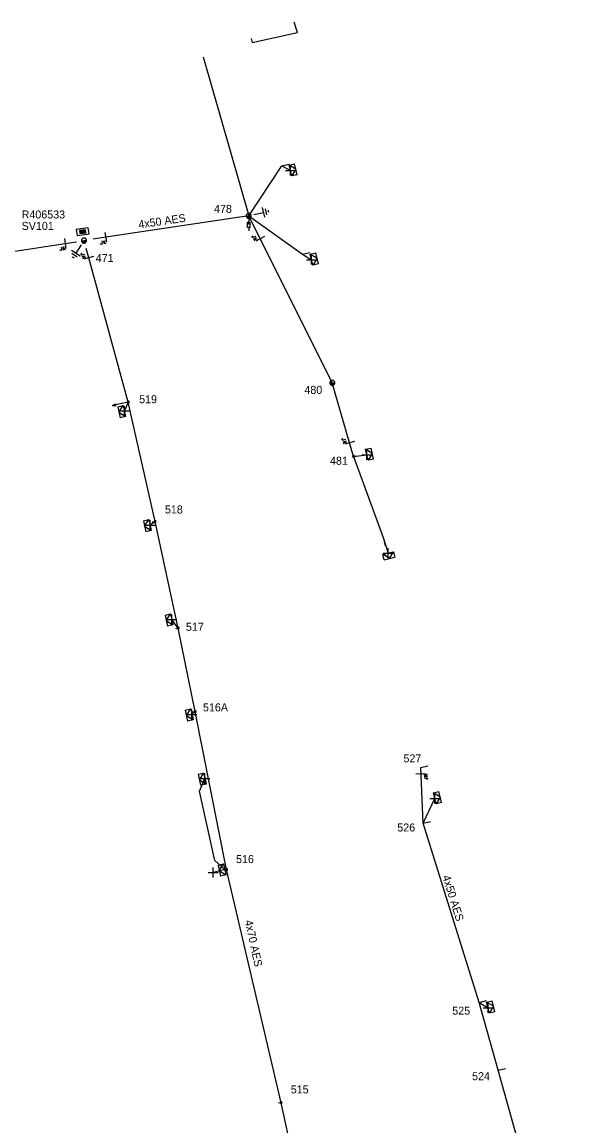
# Model space of a CAD drawing. Extents: x -540466 to -537383, y -1184038 to -1179972.
# Drawn here: x -539090.8 to -539022.6, y -1180402.2 to -1180264.3 of the extents above; entities that cross this region are included whole.
import ezdxf

# ---------------------------------------------------------------- set-up
doc = ezdxf.new("R2010")
doc.units = 0
for name, color, linetype in [('Vrstva 1', 7, 'Continuous'), ('Vrstva 13', 7, 'Continuous'), ('Vrstva 14', 7, 'Continuous'), ('Vrstva 15', 7, 'Continuous'), ('Vrstva 16', 7, 'Continuous'), ('Vrstva 18', 7, 'Continuous'), ('Vrstva 2', 7, 'Continuous'), ('Vrstva 28', 7, 'Continuous'), ('Vrstva 29', 7, 'Continuous'), ('Vrstva 30', 7, 'Continuous'), ('Vrstva 31', 7, 'Continuous'), ('Vrstva 34', 7, 'Continuous'), ('Vrstva 50', 7, 'Continuous'), ('Vrstva 51', 7, 'Continuous'), ('Vrstva 52', 7, 'Continuous'), ('Vrstva 54', 7, 'Continuous'), ('Vrstva 59', 7, 'Continuous'), ('Vrstva 8', 7, 'Continuous'), ('Vrstva 9', 7, 'Continuous')]:
    doc.layers.add(name, color=color, linetype=linetype)

# ---------------------------------------------------------------- blocks, each defined once
blk = doc.blocks.new('NN440')
at = {"layer": 'Vrstva 2'}
for points in [[(0.63, 0), (0.63, 0.06), (0.62, 0.13), (0.6, 0.19), (0.58, 0.25), (0.55, 0.31), (0.51, 0.37), (0.47, 0.42), (0.42, 0.46), (0.37, 0.51), (0.32, 0.54), (0.26, 0.57), (0.2, 0.59), (0.13, 0.61), (0.07, 0.62), (0, 0.63), (-0.06, 0.62), (-0.13, 0.61), (-0.19, 0.59), (-0.26, 0.57), (-0.31, 0.54), (-0.37, 0.51), (-0.42, 0.46), (-0.47, 0.42), (-0.51, 0.37), (-0.54, 0.31), (-0.57, 0.25), (-0.6, 0.19), (-0.62, 0.13), (-0.63, 0.06), (-0.63, 0), (-0.63, -0.07), (-0.62, -0.14), (-0.6, -0.2), (-0.57, -0.26), (-0.54, -0.32), (-0.51, -0.37), (-0.47, -0.43), (-0.42, -0.47), (-0.37, -0.51), (-0.31, -0.55), (-0.26, -0.58), (-0.19, -0.6), (-0.13, -0.62), (-0.06, -0.63), (0, -0.63), (0.07, -0.63), (0.13, -0.62), (0.2, -0.6), (0.26, -0.58), (0.32, -0.55), (0.37, -0.51), (0.42, -0.47), (0.47, -0.43), (0.51, -0.37), (0.55, -0.32), (0.58, -0.26), (0.6, -0.2), (0.62, -0.14), (0.63, -0.07), (0.63, 0)], [(-0.63, 0), (0.63, 0)], [(-0.6, -0.18), (0.57, -0.18)], [(-0.51, -0.32), (0.5, -0.32)], [(-0.37, -0.47), (0.35, -0.47)]]:
    blk.add_lwpolyline(points, dxfattribs=at)
blk = doc.blocks.new('NN560')
at = {"layer": 'Vrstva 2'}
for points in [[(2, 0), (1.59, 0.14)], [(0, 0), (2, 0)], [(2, 0), (1.59, -0.13)]]:
    blk.add_lwpolyline(points, dxfattribs=at)
blk = doc.blocks.new('NN840')
at = {"layer": 'Vrstva 15'}
for points in [[(0, 0.62), (0, -0.63)], [(-0.75, -0.71), (-0.75, -0.66)], [(-0.73, -0.76), (-0.75, -0.71)], [(-0.66, -0.8), (-0.73, -0.76)], [(-0.63, -0.8), (-0.66, -0.8)], [(-0.56, -0.76), (-0.63, -0.8)], [(-0.54, -0.71), (-0.56, -0.76)], [(-0.54, -0.38), (-0.54, -0.71)], [(-0.33, -0.38), (-0.33, -0.8)], [(-0.33, -0.64), (-0.13, -0.38)], [(-0.26, -0.56), (-0.09, -0.8)]]:
    blk.add_lwpolyline(points, dxfattribs=at)
blk = doc.blocks.new('NN800')
at = {"layer": 'Vrstva 1'}
for points in [[(-0.44, 0.44), (0.44, -0.44)], [(-0.44, -0.44), (0.44, 0.44)]]:
    blk.add_lwpolyline(points, dxfattribs=at)
blk = doc.blocks.new('NN820')
at = {"layer": 'Vrstva 13'}
for points in [[(0, 0), (0, -1.05)], [(-0.16, -0.81), (0.16, -0.81)], [(-0.16, -1.47), (-0.16, -0.81)], [(0, -1.05), (-0.06, -0.93)], [(0, -1.05), (0.06, -0.93)], [(0.16, -0.81), (0.16, -1.47)], [(0.16, -1.47), (-0.16, -1.47)], [(0, -1.47), (0, -1.87)]]:
    blk.add_lwpolyline(points, dxfattribs=at)
blk = doc.blocks.new('NN620')
at = {"layer": 'Vrstva 8'}
for points in [[(0.75, 0), (-0.75, 0)], [(-0.75, 0), (-0.75, -0.75)], [(0.75, -0.75), (0.75, 0)], [(-0.75, -0.75), (0.75, -0.75)], [(0.37, -0.18), (-0.38, -0.18)], [(-0.38, -0.18), (-0.38, -0.56)], [(-0.38, -0.56), (0.37, -0.56)], [(0.32, -0.23), (-0.33, -0.23)], [(-0.33, -0.23), (-0.33, -0.51)], [(-0.33, -0.51), (0.32, -0.51)], [(0.27, -0.27), (-0.28, -0.27)], [(-0.28, -0.27), (-0.28, -0.46)], [(-0.28, -0.46), (0.27, -0.46)], [(0.23, -0.32), (-0.23, -0.32)], [(-0.23, -0.32), (-0.23, -0.42)], [(-0.23, -0.42), (0.23, -0.42)], [(-0.19, -0.37), (0.19, -0.37)], [(0.23, -0.42), (0.23, -0.32)], [(0.27, -0.46), (0.27, -0.27)], [(0.32, -0.51), (0.32, -0.23)], [(0.37, -0.56), (0.37, -0.18)]]:
    blk.add_lwpolyline(points, dxfattribs=at)
blk = doc.blocks.new('NN630')
at = {"layer": 'Vrstva 9'}
for points in [[(0, -0.7), (-0.7, 0)], [(-0.7, -0.7), (-0.7, 0), (0.7, 0), (0.7, -0.7)], [(-0.7, -0.7), (0.7, -0.7)], [(0, -0.7), (0.7, 0)]]:
    blk.add_lwpolyline(points, dxfattribs=at)
blk = doc.blocks.new('NN810')
at = {"layer": 'Vrstva 14'}
for points in [[(0, -0.64), (0, -1.89)], [(0.63, -1.89), (-0.62, -1.89)], [(0.39, -2.2), (-0.4, -2.2)], [(0, -2.52), (-0.12, -2.52)], [(0.14, -2.52), (0, -2.52)]]:
    blk.add_lwpolyline(points, dxfattribs=at)
blk = doc.blocks.new('NN500')
at = {"layer": 'Vrstva 2'}
for points in [[(0, -0.24), (0.02, -0.23), (0.05, -0.23), (0.07, -0.22), (0.09, -0.22), (0.12, -0.2), (0.14, -0.19), (0.16, -0.18), (0.17, -0.16), (0.19, -0.14), (0.2, -0.12), (0.21, -0.1), (0.22, -0.07), (0.23, -0.05), (0.23, -0.02), (0.23, 0), (0.23, 0.02), (0.23, 0.05), (0.22, 0.07), (0.21, 0.1), (0.2, 0.12), (0.19, 0.14), (0.17, 0.16), (0.16, 0.17), (0.14, 0.19), (0.12, 0.2), (0.09, 0.21), (0.07, 0.22), (0.05, 0.23), (0.02, 0.23), (0, 0.23), (-0.03, 0.23), (-0.05, 0.23), (-0.07, 0.22), (-0.1, 0.21), (-0.12, 0.2), (-0.14, 0.19), (-0.16, 0.17), (-0.18, 0.16), (-0.19, 0.14), (-0.2, 0.12), (-0.22, 0.1), (-0.22, 0.07), (-0.23, 0.05), (-0.23, 0.02), (-0.24, 0), (-0.23, -0.02), (-0.23, -0.05), (-0.22, -0.07), (-0.22, -0.1), (-0.2, -0.12), (-0.19, -0.14), (-0.18, -0.16), (-0.16, -0.18), (-0.14, -0.19), (-0.12, -0.2), (-0.1, -0.22), (-0.07, -0.22), (-0.05, -0.23), (-0.03, -0.23), (0, -0.24)], [(0, -0.24), (0.02, -0.23), (0.05, -0.23), (0.07, -0.22), (0.09, -0.22), (0.12, -0.2), (0.14, -0.19), (0.16, -0.18), (0.17, -0.16), (0.19, -0.14), (0.2, -0.12), (0.21, -0.1), (0.22, -0.07), (0.23, -0.05), (0.23, -0.02), (0.23, 0), (0.23, 0.02), (0.23, 0.05), (0.22, 0.07), (0.21, 0.1), (0.2, 0.12), (0.19, 0.14), (0.17, 0.16), (0.16, 0.17), (0.14, 0.19), (0.12, 0.2), (0.09, 0.21), (0.07, 0.22), (0.05, 0.23), (0.02, 0.23), (0, 0.23), (-0.03, 0.23), (-0.05, 0.23), (-0.07, 0.22), (-0.1, 0.21), (-0.12, 0.2), (-0.14, 0.19), (-0.16, 0.17), (-0.18, 0.16), (-0.19, 0.14), (-0.2, 0.12), (-0.22, 0.1), (-0.22, 0.07), (-0.23, 0.05), (-0.23, 0.02), (-0.24, 0), (-0.23, -0.02), (-0.23, -0.05), (-0.22, -0.07), (-0.22, -0.1), (-0.2, -0.12), (-0.19, -0.14), (-0.18, -0.16), (-0.16, -0.18), (-0.14, -0.19), (-0.12, -0.2), (-0.1, -0.22), (-0.07, -0.22), (-0.05, -0.23), (-0.03, -0.23), (0, -0.24)], [(0, -0.21), (0.02, -0.2), (0.04, -0.2), (0.06, -0.2), (0.08, -0.19), (0.1, -0.18), (0.12, -0.17), (0.14, -0.15), (0.15, -0.14), (0.16, -0.12), (0.18, -0.1), (0.19, -0.08), (0.19, -0.06), (0.2, -0.04), (0.2, -0.02), (0.2, 0), (0.2, 0.02), (0.2, 0.04), (0.19, 0.06), (0.19, 0.08), (0.18, 0.1), (0.16, 0.12), (0.15, 0.14), (0.14, 0.15), (0.12, 0.17), (0.1, 0.18), (0.08, 0.19), (0.06, 0.19), (0.04, 0.2), (0.02, 0.2), (0, 0.2), (-0.02, 0.2), (-0.04, 0.2), (-0.06, 0.19), (-0.08, 0.19), (-0.1, 0.18), (-0.12, 0.17), (-0.14, 0.15), (-0.15, 0.14), (-0.17, 0.12), (-0.18, 0.1), (-0.19, 0.08), (-0.2, 0.06), (-0.2, 0.04), (-0.21, 0.02), (-0.21, 0), (-0.21, -0.02), (-0.2, -0.04), (-0.2, -0.06), (-0.19, -0.08), (-0.18, -0.1), (-0.17, -0.12), (-0.15, -0.14), (-0.14, -0.15), (-0.12, -0.17), (-0.1, -0.18), (-0.08, -0.19), (-0.06, -0.2), (-0.04, -0.2), (-0.02, -0.2), (0, -0.21)], [(0, -0.18), (0.02, -0.18), (0.04, -0.17), (0.05, -0.17), (0.07, -0.16), (0.09, -0.15), (0.1, -0.14), (0.12, -0.13), (0.13, -0.12), (0.14, -0.1), (0.15, -0.09), (0.16, -0.07), (0.17, -0.05), (0.17, -0.04), (0.17, -0.02), (0.17, 0), (0.17, 0.02), (0.17, 0.04), (0.17, 0.05), (0.16, 0.07), (0.15, 0.09), (0.14, 0.1), (0.13, 0.12), (0.12, 0.13), (0.1, 0.14), (0.09, 0.15), (0.07, 0.16), (0.05, 0.17), (0.04, 0.17), (0.02, 0.17), (0, 0.18), (-0.02, 0.17), (-0.04, 0.17), (-0.06, 0.17), (-0.07, 0.16), (-0.09, 0.15), (-0.1, 0.14), (-0.12, 0.13), (-0.13, 0.12), (-0.14, 0.1), (-0.15, 0.09), (-0.16, 0.07), (-0.17, 0.05), (-0.17, 0.04), (-0.18, 0.02), (-0.18, 0), (-0.18, -0.02), (-0.17, -0.04), (-0.17, -0.05), (-0.16, -0.07), (-0.15, -0.09), (-0.14, -0.1), (-0.13, -0.12), (-0.12, -0.13), (-0.1, -0.14), (-0.09, -0.15), (-0.07, -0.16), (-0.06, -0.17), (-0.04, -0.17), (-0.02, -0.18), (0, -0.18)], [(0, -0.15), (0.01, -0.15), (0.03, -0.14), (0.04, -0.14), (0.06, -0.13), (0.07, -0.13), (0.08, -0.12), (0.1, -0.11), (0.11, -0.1), (0.12, -0.09), (0.13, -0.07), (0.13, -0.06), (0.14, -0.05), (0.14, -0.03), (0.14, -0.02), (0.14, 0), (0.14, 0.01), (0.14, 0.03), (0.14, 0.04), (0.13, 0.06), (0.13, 0.07), (0.12, 0.09), (0.11, 0.1), (0.1, 0.11), (0.08, 0.12), (0.07, 0.13), (0.06, 0.13), (0.04, 0.14), (0.03, 0.14), (0.01, 0.14), (0, 0.15), (-0.02, 0.14), (-0.03, 0.14), (-0.05, 0.14), (-0.06, 0.13), (-0.07, 0.13), (-0.09, 0.12), (-0.1, 0.11), (-0.11, 0.1), (-0.12, 0.09), (-0.13, 0.07), (-0.13, 0.06), (-0.14, 0.04), (-0.14, 0.03), (-0.15, 0.01), (-0.15, 0), (-0.15, -0.02), (-0.14, -0.03), (-0.14, -0.05), (-0.13, -0.06), (-0.13, -0.07), (-0.12, -0.09), (-0.11, -0.1), (-0.1, -0.11), (-0.09, -0.12), (-0.07, -0.13), (-0.06, -0.13), (-0.05, -0.14), (-0.03, -0.14), (-0.02, -0.15), (0, -0.15)], [(0, -0.12), (0.01, -0.12), (0.02, -0.11), (0.03, -0.11), (0.05, -0.11), (0.06, -0.1), (0.07, -0.09), (0.08, -0.09), (0.09, -0.08), (0.09, -0.07), (0.1, -0.06), (0.11, -0.05), (0.11, -0.04), (0.11, -0.02), (0.11, -0.01), (0.12, 0), (0.11, 0.01), (0.11, 0.02), (0.11, 0.04), (0.11, 0.05), (0.1, 0.06), (0.09, 0.07), (0.09, 0.08), (0.08, 0.09), (0.07, 0.09), (0.06, 0.1), (0.05, 0.11), (0.03, 0.11), (0.02, 0.11), (0.01, 0.12), (0, 0.12), (-0.01, 0.12), (-0.03, 0.11), (-0.04, 0.11), (-0.05, 0.11), (-0.06, 0.1), (-0.07, 0.09), (-0.08, 0.09), (-0.09, 0.08), (-0.1, 0.07), (-0.1, 0.06), (-0.11, 0.05), (-0.11, 0.04), (-0.12, 0.02), (-0.12, 0.01), (-0.12, 0), (-0.12, -0.01), (-0.12, -0.02), (-0.11, -0.04), (-0.11, -0.05), (-0.1, -0.06), (-0.1, -0.07), (-0.09, -0.08), (-0.08, -0.09), (-0.07, -0.09), (-0.06, -0.1), (-0.05, -0.11), (-0.04, -0.11), (-0.03, -0.11), (-0.01, -0.12), (0, -0.12)], [(0, -0.09), (0.01, -0.09), (0.02, -0.09), (0.03, -0.08), (0.03, -0.08), (0.04, -0.08), (0.05, -0.07), (0.06, -0.07), (0.06, -0.06), (0.07, -0.05), (0.07, -0.04), (0.08, -0.04), (0.08, -0.03), (0.08, -0.02), (0.09, -0.01), (0.09, 0), (0.09, 0.01), (0.08, 0.02), (0.08, 0.03), (0.08, 0.03), (0.07, 0.04), (0.07, 0.05), (0.06, 0.06), (0.06, 0.06), (0.05, 0.07), (0.04, 0.07), (0.03, 0.08), (0.03, 0.08), (0.02, 0.08), (0.01, 0.09), (0, 0.09), (-0.01, 0.09), (-0.02, 0.08), (-0.03, 0.08), (-0.04, 0.08), (-0.04, 0.07), (-0.05, 0.07), (-0.06, 0.06), (-0.07, 0.06), (-0.07, 0.05), (-0.08, 0.04), (-0.08, 0.03), (-0.08, 0.03), (-0.09, 0.02), (-0.09, 0.01), (-0.09, 0), (-0.09, -0.01), (-0.09, -0.02), (-0.08, -0.03), (-0.08, -0.04), (-0.08, -0.04), (-0.07, -0.05), (-0.07, -0.06), (-0.06, -0.07), (-0.05, -0.07), (-0.04, -0.08), (-0.04, -0.08), (-0.03, -0.08), (-0.02, -0.09), (-0.01, -0.09), (0, -0.09)], [(0, -0.06), (0, -0.06), (0.01, -0.06), (0.02, -0.05), (0.02, -0.05), (0.03, -0.05), (0.03, -0.05), (0.04, -0.04), (0.04, -0.04), (0.05, -0.03), (0.05, -0.03), (0.05, -0.02), (0.05, -0.02), (0.05, -0.01), (0.06, -0.01), (0.06, 0), (0.06, 0.01), (0.05, 0.01), (0.05, 0.02), (0.05, 0.02), (0.05, 0.03), (0.05, 0.03), (0.04, 0.04), (0.04, 0.04), (0.03, 0.05), (0.03, 0.05), (0.02, 0.05), (0.02, 0.05), (0.01, 0.06), (0, 0.06), (0, 0.06), (-0.01, 0.06), (-0.01, 0.06), (-0.02, 0.05), (-0.02, 0.05), (-0.03, 0.05), (-0.03, 0.05), (-0.04, 0.04), (-0.04, 0.04), (-0.05, 0.03), (-0.05, 0.03), (-0.05, 0.02), (-0.06, 0.02), (-0.06, 0.01), (-0.06, 0.01), (-0.06, 0), (-0.06, -0.01), (-0.06, -0.01), (-0.06, -0.02), (-0.05, -0.02), (-0.05, -0.03), (-0.05, -0.03), (-0.04, -0.04), (-0.04, -0.04), (-0.03, -0.05), (-0.03, -0.05), (-0.02, -0.05), (-0.02, -0.05), (-0.01, -0.06), (-0.01, -0.06), (0, -0.06)], [(0, -0.03), (0, -0.03), (0, -0.03), (0.01, -0.03), (0.01, -0.03), (0.01, -0.02), (0.02, -0.02), (0.02, -0.02), (0.02, -0.02), (0.02, -0.02), (0.02, -0.01), (0.02, -0.01), (0.03, -0.01), (0.03, -0.01), (0.03, 0), (0.03, 0), (0.03, 0), (0.03, 0.01), (0.03, 0.01), (0.02, 0.01), (0.02, 0.01), (0.02, 0.02), (0.02, 0.02), (0.02, 0.02), (0.02, 0.02), (0.01, 0.02), (0.01, 0.02), (0.01, 0.03), (0, 0.03), (0, 0.03), (0, 0.03), (0, 0.03), (-0.01, 0.03), (-0.01, 0.03), (-0.01, 0.02), (-0.02, 0.02), (-0.02, 0.02), (-0.02, 0.02), (-0.02, 0.02), (-0.02, 0.02), (-0.03, 0.01), (-0.03, 0.01), (-0.03, 0.01), (-0.03, 0.01), (-0.03, 0), (-0.03, 0), (-0.03, 0), (-0.03, -0.01), (-0.03, -0.01), (-0.03, -0.01), (-0.03, -0.01), (-0.02, -0.02), (-0.02, -0.02), (-0.02, -0.02), (-0.02, -0.02), (-0.02, -0.02), (-0.01, -0.03), (-0.01, -0.03), (-0.01, -0.03), (0, -0.03), (0, -0.03)], [(0.23, 0), (0.7, 0)]]:
    blk.add_lwpolyline(points, dxfattribs=at)
blk = doc.blocks.new('NN510')
at = {"layer": 'Vrstva 2'}
blk.add_lwpolyline([(0, 0), (0, 0.94)], dxfattribs=at)

msp = doc.modelspace()

# ---------------------------------------------------------------- linework, layer by layer
at = {"layer": 'Vrstva 50'}
for points in [[(-539068.11, -1180268.64), (-539062.44, -1180288.49)], [(-539062.44, -1180288.49), (-539080.31, -1180291.17), (-539081.87, -1180291.41)], [(-539146.42, -1180302.53), (-539117.6, -1180296.87), (-539085.38, -1180291.94), (-539083.95, -1180291.72)], [(-539056.32, -1180408.67), (-539058.39, -1180399.32), (-539065.2, -1180370.19), (-539069.12, -1180350.45), (-539071.24, -1180340.01), (-539074.14, -1180326.71), (-539077.49, -1180311.78), (-539082.43, -1180293.73), (-539082.75, -1180292.58)], [(-539022.55, -1180455.54), (-539022.63, -1180454.15), (-539024.54, -1180420.07), (-539028.02, -1180406.89), (-539031.25, -1180395.27), (-539033.65, -1180386.8), (-539040.65, -1180364.39), (-539040.95, -1180357.43)]]:
    msp.add_lwpolyline(points, dxfattribs=at)
at = {"layer": 'Vrstva 52'}
for points in [[(-539062.14, -1180266.35), (-539062.01, -1180266.82), (-539056.34, -1180265.6), (-539056.74, -1180264.28)], [(-539049.33, -1180318.56), (-539051.99, -1180309.36), (-539062.44, -1180288.49)]]:
    msp.add_lwpolyline(points, dxfattribs=at)
at = {"layer": 'Vrstva 54'}
for points in [[(-539062.44, -1180288.49), (-539058.31, -1180282.23), (-539057.23, -1180282.83)], [(-539062.44, -1180288.49), (-539055.7, -1180293.3), (-539054.58, -1180293.97)], [(-539077.49, -1180311.78), (-539077.97, -1180312.88)], [(-539049.33, -1180318.56), (-539047.68, -1180318.35)], [(-539049.33, -1180318.56), (-539045.59, -1180328.83), (-539045.01, -1180330.63)], [(-539074.14, -1180326.71), (-539074.76, -1180327.13)], [(-539065.2, -1180370.19), (-539065.43, -1180370.17)]]:
    msp.add_lwpolyline(points, dxfattribs=at)
at = {"layer": 'Vrstva 59'}
for points in [[(-539065.43, -1180370.17), (-539066.67, -1180369.07), (-539068.58, -1180360.38), (-539067.91, -1180358.81)], [(-539065.43, -1180370.17), (-539066.87, -1180370.55)]]:
    msp.add_lwpolyline(points, dxfattribs=at)
at = {"layer": 'Vrstva 8'}
for points in [[(-539071.24, -1180340.01), (-539072.06, -1180338.92)], [(-539069.12, -1180350.45), (-539069.53, -1180350.8)], [(-539040.65, -1180364.39), (-539039.19, -1180361.29)], [(-539033.65, -1180386.8), (-539032.53, -1180387.45)]]:
    msp.add_lwpolyline(points, dxfattribs=at)

# ---------------------------------------------------------------- block references
at = {"layer": 'Vrstva 13'}
for name, p, rotation in [('NN510', (-539058.31, -1180282.23), -76.70279993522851), ('NN510', (-539055.7, -1180293.3), -76.40452785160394), ('NN560', (-539077.49, -1180311.78), -167.98613612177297), ('NN510', (-539045.59, -1180328.83), -166.53636109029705), ('NN510', (-539040.95, -1180357.43), -76.89796104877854), ('NN510', (-539040.65, -1180364.39), -76.91743335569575), ('NN510', (-539033.65, -1180386.8), -75.53231110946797), ('NN510', (-539031.26, -1180395.27), -75.53231110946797)]:
    msp.add_blockref(name, p, dxfattribs=dict(at, rotation=rotation))
at = {"layer": 'Vrstva 13', "xscale": 0.5, "yscale": 0.5}
for p in [(-539062.44, -1180288.49), (-539051.99, -1180309.36)]:
    msp.add_blockref('NN440', p, dxfattribs=at)
at = {"layer": 'Vrstva 13'}
for name, p, xscale, yscale, rotation in [('NN440', (-539083.02, -1180291.58), 0.5000000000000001, 0.5, 8.973777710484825), ('NN500', (-539077.49, -1180311.78), 0.5, 0.5, -167.9859999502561), ('NN500', (-539049.33, -1180318.56), 0.5, 0.5, 12.54900005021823), ('NN500', (-539074.14, -1180326.71), 0.49999999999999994, 0.5000000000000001, -167.25400006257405), ('NN500', (-539071.24, -1180340.01), 0.5, 0.5, -167.79500002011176), ('NN500', (-539069.12, -1180350.45), 0.5, 0.5, -169.0469067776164), ('NN500', (-539065.2, -1180370.19), 0.49999999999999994, 0.5, -167.5850000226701), ('NN500', (-539058.39, -1180399.32), 0.5, 0.5, -167.47900001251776)]:
    msp.add_blockref(name, p, dxfattribs=dict(at, xscale=xscale, yscale=yscale, rotation=rotation))
at = {"layer": 'Vrstva 15'}
for p, rotation in [((-539062.44, -1180288.49), 103.29719996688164), ((-539083.02, -1180291.58), -32.70939725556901)]:
    msp.add_blockref('NN810', p, dxfattribs=dict(at, rotation=rotation))
at = {"layer": 'Vrstva 16'}
msp.add_blockref('NN820', (-539062.44, -1180288.49), dxfattribs=at)
at = {"layer": 'Vrstva 18'}
for p, rotation in [((-539085.38, -1180291.94), 8.698947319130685), ((-539080.31, -1180291.17), 8.531174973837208), ((-539061, -1180291.37), -63.38773611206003), ((-539082.43, -1180293.73), -74.6868194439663), ((-539049.82, -1180316.86), -73.90675280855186), ((-539040.92, -1180358.21), 92.45919449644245)]:
    msp.add_blockref('NN840', p, dxfattribs=dict(at, rotation=rotation))
at = {"layer": 'Vrstva 28', "rotation": -171.49400004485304}
msp.add_blockref('NN620', (-539083.13, -1180290.84), dxfattribs=at)
at = {"layer": 'Vrstva 31'}
for p, rotation in [((-539057.23, -1180282.83), 103.29720006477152), ((-539054.58, -1180293.97), 103.59547214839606), ((-539077.97, -1180312.88), -77.33053332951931), ((-539047.68, -1180318.35), 102.54918892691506), ((-539074.76, -1180327.13), -77.25431104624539), ((-539045.01, -1180330.63), 13.463638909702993), ((-539072.06, -1180338.92), -77.79516390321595), ((-539069.53, -1180350.8), -77.70142239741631), ((-539067.91, -1180358.81), -78.10049727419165), ((-539039.19, -1180361.29), 103.1020388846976), ((-539065.43, -1180370.17), -77.58485275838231), ((-539032.53, -1180387.45), 104.46768889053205)]:
    msp.add_blockref('NN630', p, dxfattribs=dict(at, rotation=rotation))
at = {"layer": 'Vrstva 34'}
for p, rotation in [((-539057.23, -1180282.83), 45), ((-539054.58, -1180293.97), 44.99999995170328), ((-539077.97, -1180312.88), 45), ((-539047.68, -1180318.35), 44.99999995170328), ((-539074.76, -1180327.13), 45), ((-539045.01, -1180330.63), 45.00000009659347), ((-539072.06, -1180338.92), 45), ((-539069.53, -1180350.8), 45), ((-539067.91, -1180358.81), 45), ((-539039.19, -1180361.29), 45), ((-539066.87, -1180370.55), 45.000000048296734), ((-539032.53, -1180387.45), 45)]:
    msp.add_blockref('NN800', p, dxfattribs=dict(at, rotation=rotation))

# ---------------------------------------------------------------- texts
at = {"layer": 'Vrstva 14'}
for s, p in [('478', (-539066.77, -1180288.12)), ('471', (-539081.55, -1180294.26)), ('480', (-539055.48, -1180310.74)), ('519', (-539076.13, -1180311.91)), ('481', (-539052.28, -1180319.6)), ('518', (-539072.91, -1180325.69)), ('517', (-539070.28, -1180340.35)), ('516A', (-539068.15, -1180350.42)), ('527', (-539043.1, -1180356.79)), ('526', (-539043.87, -1180365.43)), ('516', (-539064.02, -1180369.38)), ('525', (-539037, -1180388.32)), ('524', (-539034.53, -1180396.51)), ('515', (-539057.18, -1180398.16))]:
    msp.add_text(s, height=1, dxfattribs=at).set_placement(p)
at = {"layer": 'Vrstva 29'}
msp.add_text('R406533', height=1, dxfattribs=at).set_placement((-539090.81, -1180288.82))
at = {"layer": 'Vrstva 30'}
msp.add_text('SV101', height=1, dxfattribs=at).set_placement((-539090.81, -1180290.25))
at = {"layer": 'Vrstva 51'}
for s, rotation, p in [('4x50 AES', 8.365, (-539076.14, -1180290.08)), ('4x50 AES', 287.353, (-539038.25, -1180371.06)), ('4x70 AES', 282.207, (-539062.94, -1180376.6))]:
    msp.add_text(s, height=1, rotation=rotation, dxfattribs=at).set_placement(p)

doc.saveas('drawing.dxf')
